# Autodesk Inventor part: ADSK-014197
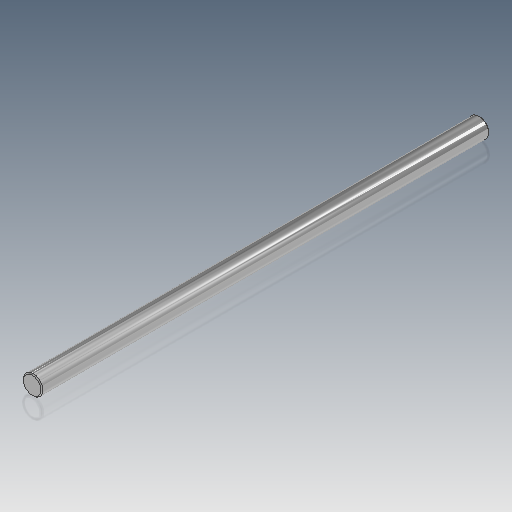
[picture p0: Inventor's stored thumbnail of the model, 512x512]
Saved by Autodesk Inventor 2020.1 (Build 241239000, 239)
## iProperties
Created: 1999-12
Part Number: ADSK-014197
Material: Acier doux
Description: SHFT-T,TH,AX,07-06,188,ADJUST,WIDTH,LH
Document SubType Name: Modeling
Designer: sspink
Density: 7.86 g/cm^3
Appearance: Chrom - poliert
Mass: 1130.46 g
Surface Area: 293.291 cm^2
Volume: 143.824 cm^3
Control State: 0
Master: False
Checked Out: False
Shininess: 0.0
Length Units: 11269
Angle Units: 11279
Time Units: 11290
Mass Units: 11283
Length Display Precision: 3
Angle Display Precision: 2
Compacted: True
Cutlength: 18.81
Material Desc: THREADED-ROD,0.750-06LH ACME
Material_number: A084662
Dimensions: 20x20x458 mm
Mass: 1,13 kg
DocNumber: ADSK-014197
Folder: 01 - Themengebiete\Simplification\01 - Packaging machine\
Original: C:\AB_Vault\CAD\01 - Themengebiete\Simplification\01 - Packaging machine\Parts\ADSK-011337.ipt
VDS_Category: 3D Komponenten
VDS_NumSchm: Autodesk
Density: 0.0
Volumn: 0.0
Area: 0.0
PropertySet Name: Model Information
Author: sspink
Revision Number: -
Title: shaft
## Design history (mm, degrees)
node "Solide1"
  node "Extrusion1" dims "d1" = 458, "d2" = 0
sketch "Sketch1"
  geometry: C1 r 10 at (0, 0); 1 further point
  constraints: 1 centre point, 1 coincident
  dimensions: "d0" = 20 diameter of C1
chamfer "Fase1" distance "d3" = 1; stored, may be unused: second distance "d4" = 2, angle "d5" = 45 deg
node "Corps solides"
node "Corps surfaciques"
